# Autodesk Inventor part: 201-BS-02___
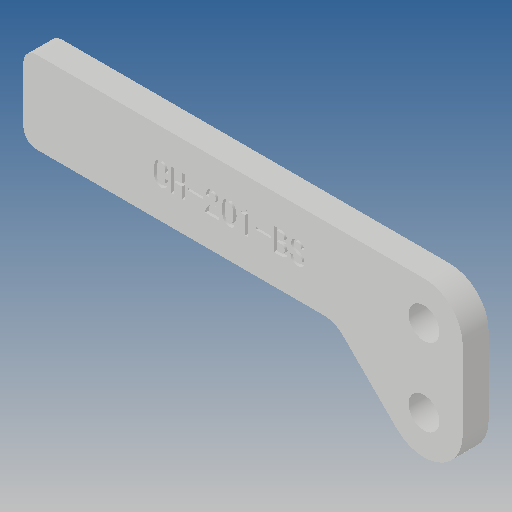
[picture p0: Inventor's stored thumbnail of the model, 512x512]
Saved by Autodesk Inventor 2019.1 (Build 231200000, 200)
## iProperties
Created: 2010-06
Part Number: 201-BS-02___
Material: Ogólny
Document SubType Name: Modeling
Designer: CADENGINEERING4
Density: 1 g/cm^3
Appearance: Domyślna
Author: CADENGINEERING4
Revision Number: ANY
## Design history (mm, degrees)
feature "NONE"
node "Bryła1"
